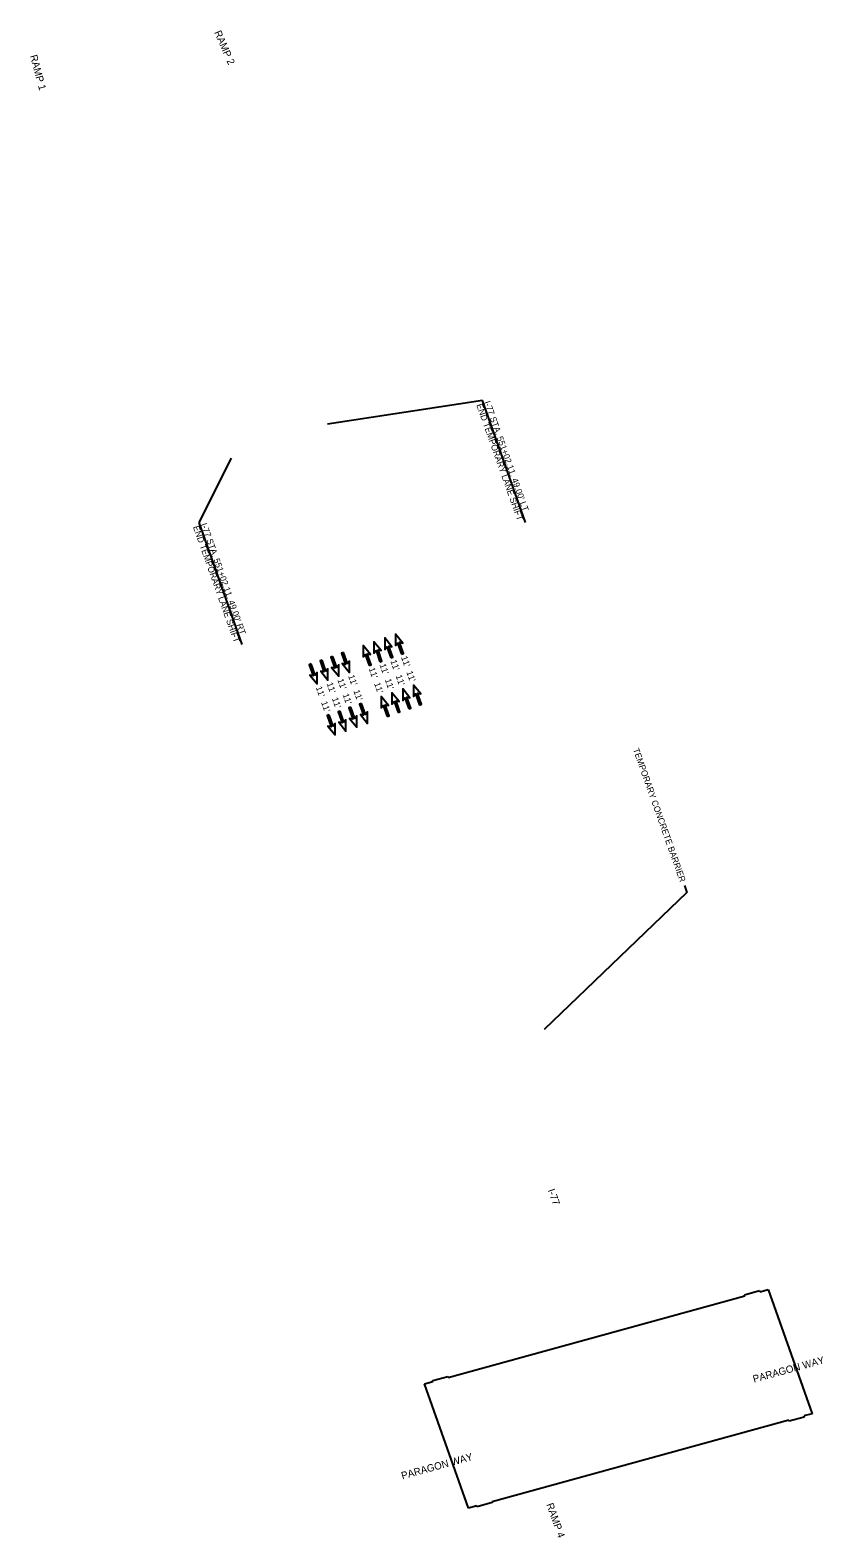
# Model space of a CAD drawing. Extents: x 2004770 to 2007199, y 1133765 to 1140032.
# Drawn here: x 2005369 to 2006131, y 1136961 to 1138411 of the extents above; entities that cross this region are included whole.
import ezdxf

# ---------------------------------------------------------------- set-up
doc = ezdxf.new("R2010")
doc.units = 0
for name, color, linetype in [('RD_PD_ALT1_LnLine', 7, 'Continuous'), ('RD_PD_MedBWall', 7, 'Continuous'), ('RD_XS_Base', 7, 'Continuous')]:
    doc.layers.add(name, color=color, linetype=linetype)

msp = doc.modelspace()

# ---------------------------------------------------------------- linework, layer by layer
at = {"layer": 'RD_PD_ALT1_LnLine'}
for p, q in [((2005770.4, 1137115.7), (2006055.6, 1137194.2)), ((2006055.3, 1137195.1), (2006069.8, 1137199.1)), ((2006055.6, 1137194.2), (2006055.3, 1137195.1)), ((2006069.8, 1137199.1), (2006070.1, 1137198.1)), ((2006070.1, 1137198.1), (2006077.9, 1137200.3)), ((2006077.9, 1137200.3), (2006120.2, 1137080.7)), ((2005755.7, 1137112.6), (2005770.1, 1137116.6)), ((2005770.1, 1137116.6), (2005770.4, 1137115.7)), ((2005747.9, 1137109.5), (2005755.9, 1137111.7)), ((2005790.2, 1136989.9), (2005747.9, 1137109.5)), ((2005755.9, 1137111.7), (2005755.7, 1137112.6)), ((2006097.9, 1137074.6), (2005812.7, 1136996.1)), ((2006098.2, 1137073.6), (2006097.9, 1137074.6)), ((2006112.6, 1137077.6), (2006098.2, 1137073.6)), ((2006120.2, 1137080.7), (2006112.4, 1137078.6)), ((2006112.4, 1137078.6), (2006112.6, 1137077.6)), ((2005798.2, 1136992.1), (2005790.2, 1136989.9)), ((2005798.4, 1136991.3), (2005798.2, 1136992.1)), ((2005812.9, 1136995.3), (2005798.4, 1136991.3)), ((2005812.7, 1136996.1), (2005812.9, 1136995.3))]:
    msp.add_line(p, q, dxfattribs=at)
at = {"layer": 'RD_PD_MedBWall'}
for p, q in [((2005844.9, 1137937.7), (2005803.5, 1138054.9)), ((2005572.6, 1137820.4), (2005531.1, 1137937.6))]:
    msp.add_line(p, q, dxfattribs=at)
for points in [[(2005803.5, 1138054.9), (2005654.6, 1138032.2)], [(2005531.1, 1137937.6), (2005562.2, 1137999.5)], [(2005997.5, 1137588.6), (2005999.8, 1137581.9), (2005862.7, 1137450.1)]]:
    msp.add_lwpolyline(points, dxfattribs=at)
for points in [[(2005715.3, 1137807.5), (2005717.2, 1137808.1), (2005713.4, 1137818.8), (2005716.5, 1137818.1), (2005709.6, 1137826.7), (2005709.6, 1137815.7), (2005711.5, 1137818.2)], [(2005725.7, 1137811.1), (2005727.6, 1137811.8), (2005723.8, 1137822.5), (2005726.9, 1137821.8), (2005720, 1137830.3), (2005720, 1137819.4), (2005721.9, 1137821.8)], [(2005670, 1137812.7), (2005668.1, 1137812), (2005671.9, 1137801.3), (2005668.8, 1137802), (2005675.7, 1137793.5), (2005675.7, 1137804.4), (2005673.8, 1137802)], [(2005694.6, 1137800.1), (2005696.5, 1137800.8), (2005692.7, 1137811.5), (2005695.8, 1137810.8), (2005688.9, 1137819.3), (2005688.8, 1137808.4), (2005690.8, 1137810.8)], [(2005704.9, 1137803.8), (2005706.8, 1137804.5), (2005703.1, 1137815.2), (2005706.1, 1137814.5), (2005699.2, 1137823), (2005699.2, 1137812), (2005701.2, 1137814.5)], [(2005638.9, 1137801.7), (2005637, 1137801), (2005640.8, 1137790.3), (2005637.7, 1137791), (2005644.6, 1137782.5), (2005644.6, 1137793.4), (2005642.7, 1137791)], [(2005649.3, 1137805.3), (2005647.4, 1137804.7), (2005651.1, 1137794), (2005648.1, 1137794.7), (2005655, 1137786.1), (2005655, 1137797.1), (2005653, 1137794.6)], [(2005659.6, 1137809), (2005657.7, 1137808.3), (2005661.5, 1137797.6), (2005658.5, 1137798.3), (2005665.4, 1137789.8), (2005665.4, 1137800.8), (2005663.4, 1137798.3)], [(2005743, 1137762.2), (2005744.9, 1137762.9), (2005741.1, 1137773.5), (2005744.2, 1137772.9), (2005737.3, 1137781.4), (2005737.3, 1137770.4), (2005739.2, 1137772.9)], [(2005711.9, 1137751.2), (2005713.8, 1137751.9), (2005710, 1137762.5), (2005713.1, 1137761.9), (2005706.2, 1137770.4), (2005706.2, 1137759.4), (2005708.1, 1137761.9)], [(2005722.3, 1137754.9), (2005724.2, 1137755.5), (2005720.4, 1137766.2), (2005723.4, 1137765.5), (2005716.5, 1137774), (2005716.5, 1137763.1), (2005718.5, 1137765.5)], [(2005732.6, 1137758.5), (2005734.5, 1137759.2), (2005730.7, 1137769.9), (2005733.8, 1137769.2), (2005726.9, 1137777.7), (2005726.9, 1137766.7), (2005728.9, 1137769.2)], [(2005656.2, 1137752.7), (2005654.3, 1137752), (2005658.1, 1137741.3), (2005655, 1137742), (2005661.9, 1137733.5), (2005661.9, 1137744.5), (2005660, 1137742)], [(2005666.6, 1137756.4), (2005664.7, 1137755.7), (2005668.5, 1137745), (2005665.4, 1137745.7), (2005672.3, 1137737.2), (2005672.3, 1137748.1), (2005670.4, 1137745.7)], [(2005676.9, 1137760), (2005675.1, 1137759.4), (2005678.8, 1137748.7), (2005675.8, 1137749.4), (2005682.7, 1137740.8), (2005682.7, 1137751.8), (2005680.7, 1137749.3)], [(2005687.3, 1137763.7), (2005685.4, 1137763), (2005689.2, 1137752.4), (2005686.1, 1137753), (2005693, 1137744.5), (2005693.1, 1137755.5), (2005691.1, 1137753)]]:
    msp.add_lwpolyline(points, close=True, dxfattribs=at)

# ---------------------------------------------------------------- texts
for s, p in [('END TEMPORARY LANE SHIFT', (2005797.5, 1138050.7)), ("I-77 STA. 551+02.11, 49.00' LT", (2005805.1, 1138053.4)), ('END TEMPORARY LANE SHIFT', (2005525.2, 1137933.4)), ("I-77 STA. 551+02.11, 49.00' RT", (2005532.8, 1137936)), ("11'", (2005694.1, 1137797.1)), ("11'", (2005704.5, 1137800.8)), ("11'", (2005714.9, 1137804.5)), ("11'", (2005725.2, 1137808.1)), ("11'", (2005653.6, 1137782.8)), ("11'", (2005664, 1137786.4)), ("11'", (2005674.3, 1137790.1)), ("11'", (2005699.2, 1137782.8)), ("11'", (2005709.6, 1137786.4)), ("11'", (2005720, 1137790.1)), ("11'", (2005730.3, 1137793.8)), ("11'", (2005643.2, 1137779.1)), ("11'", (2005658.7, 1137768.4)), ("11'", (2005669, 1137772.1)), ("11'", (2005679.4, 1137775.7)), ("11'", (2005648.3, 1137764.7)), ('TEMPORARY CONCRETE BARRIER', (2005948, 1137719.5))]:
    msp.add_text(s, height=6, rotation=289.482, dxfattribs=at).set_placement(p)
at = {"layer": 'RD_XS_Base'}
for s, rotation, p in [('RAMP 2', 293.3517, (2005545.6, 1138409)), ('RAMP 1', 285.0109, (2005368.6, 1138386.4)), ('I-77', 289.482, (2005866.2, 1137295.7)), ('PARAGON WAY', 15.3889, (2006064.4, 1137110.6)), ('PARAGON WAY', 15.3889, (2005726.5, 1137017.6)), ('RAMP 4', 289.482, (2005864.7, 1136993.5))]:
    msp.add_text(s, height=7, rotation=rotation, dxfattribs=at).set_placement(p)

doc.saveas('drawing.dxf')
